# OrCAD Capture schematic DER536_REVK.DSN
size C; title: DER 536; rev: B
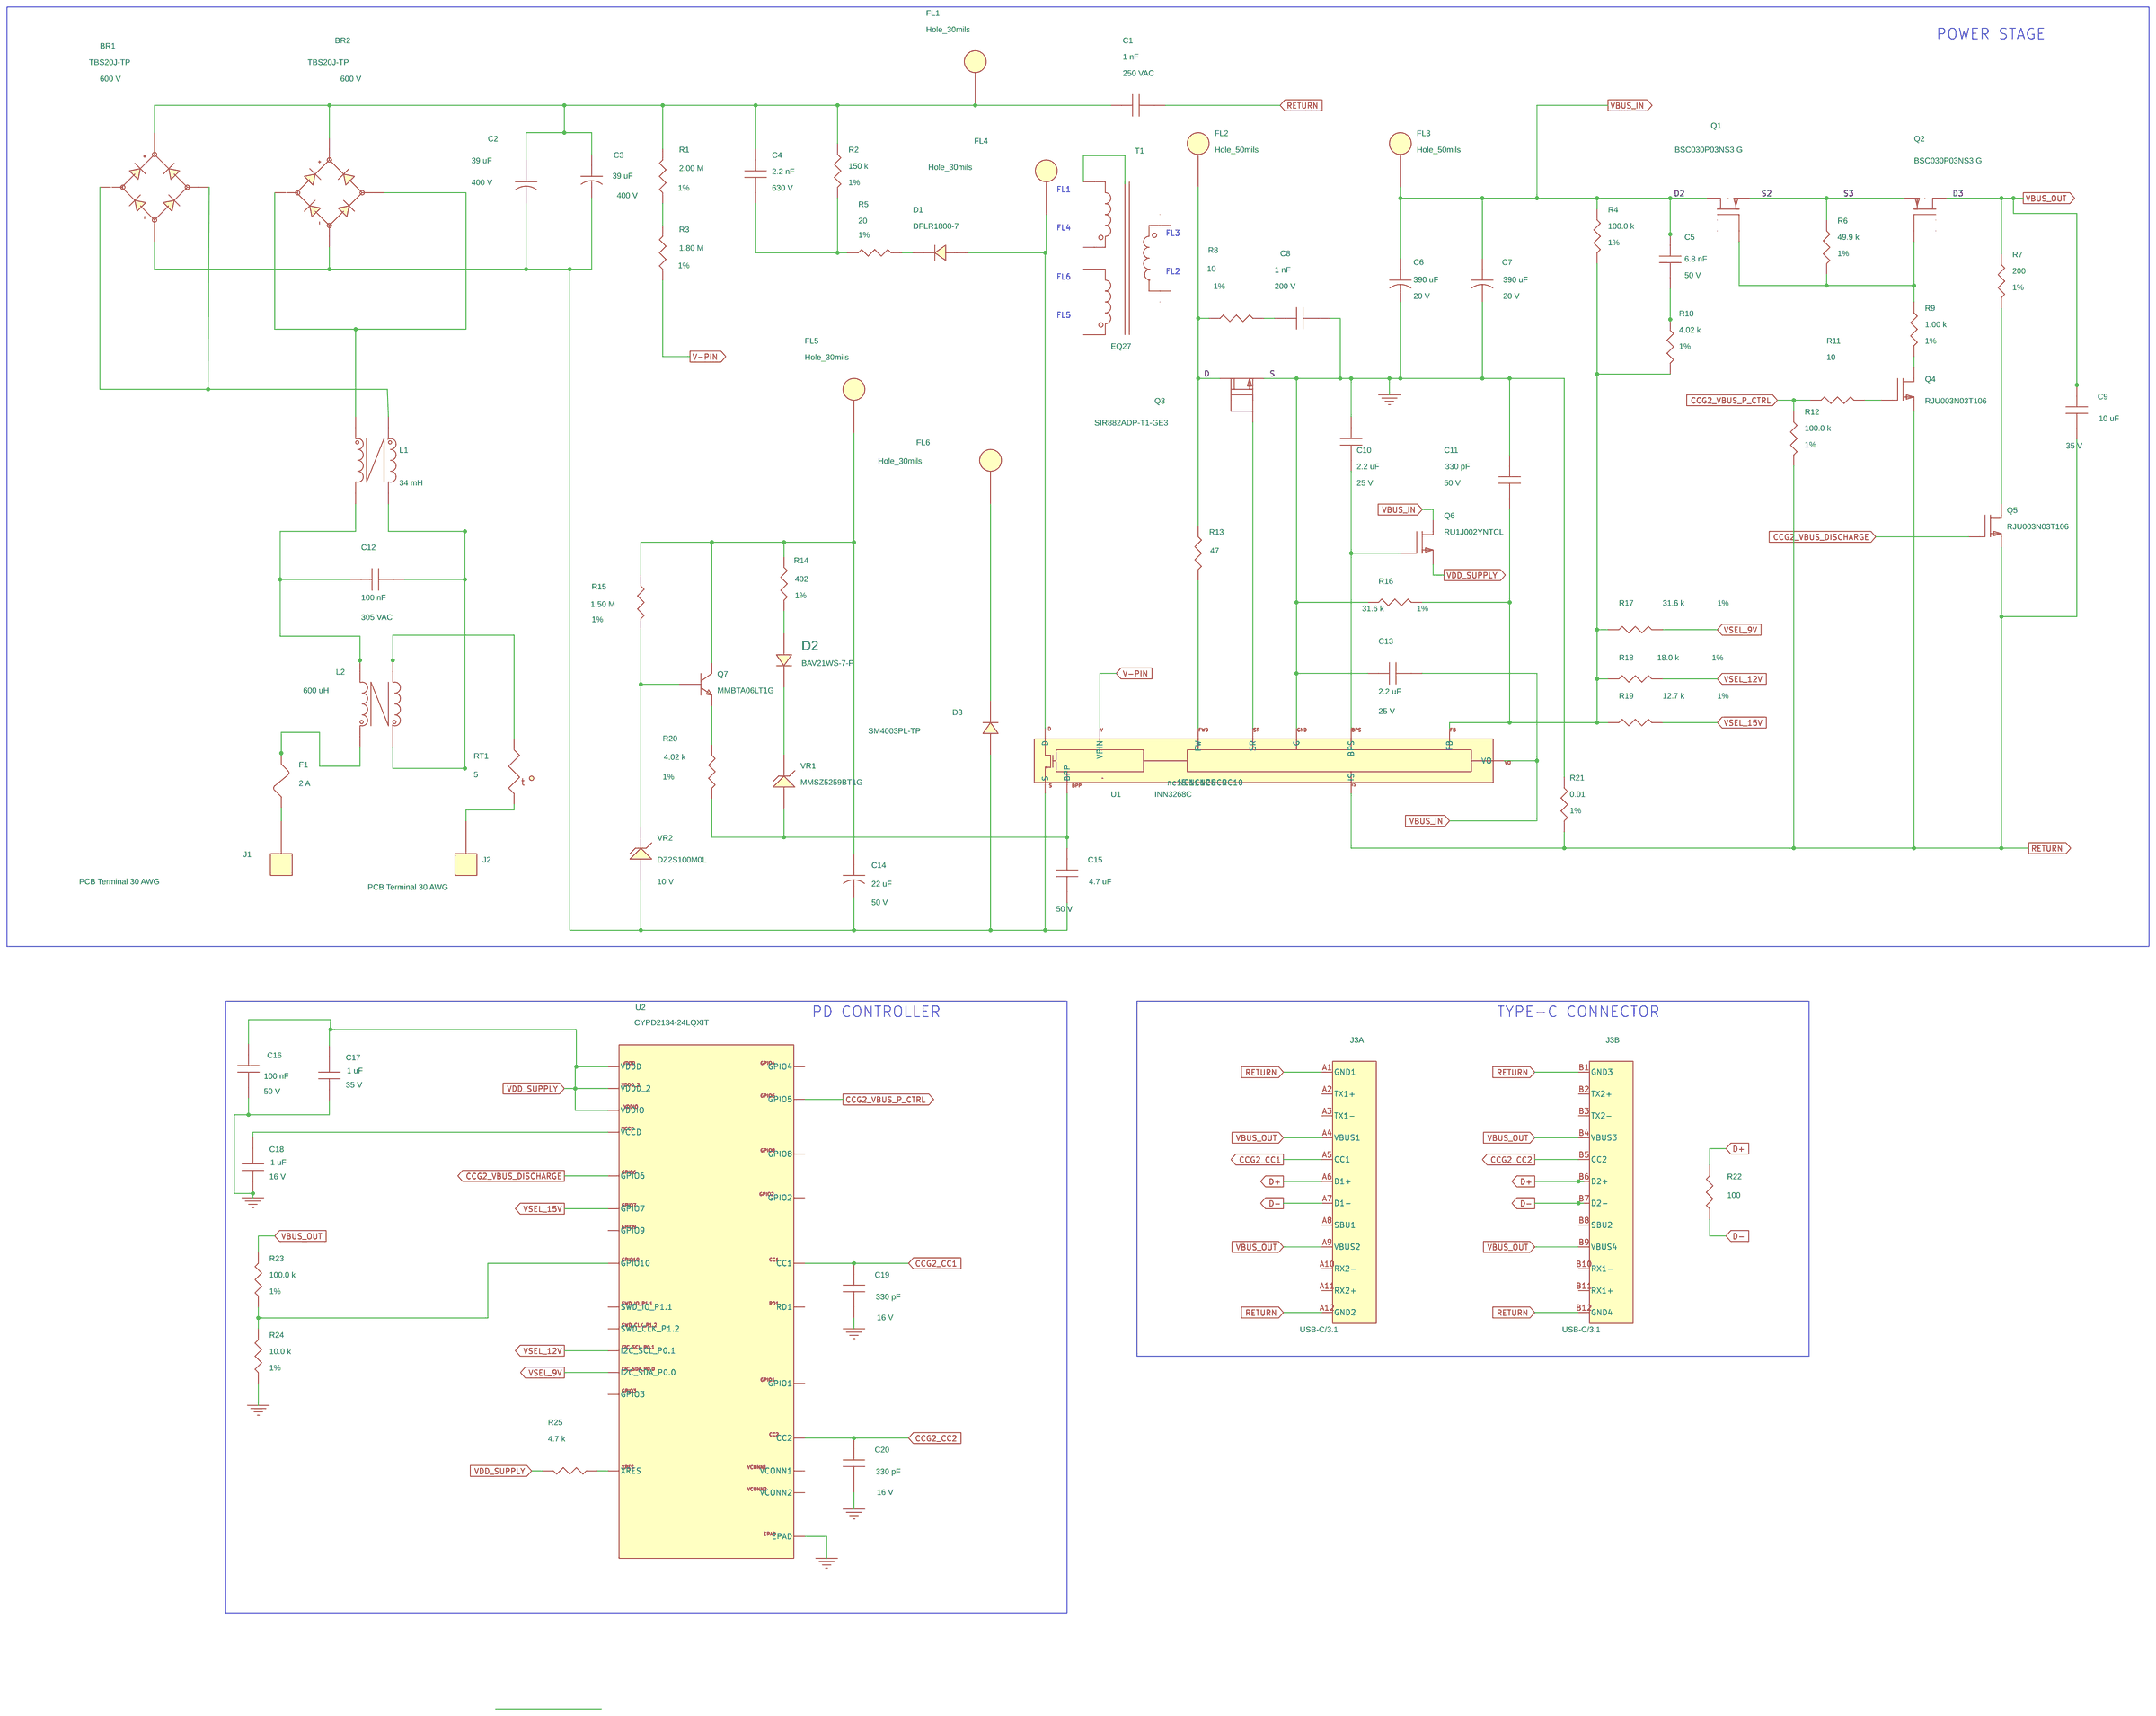
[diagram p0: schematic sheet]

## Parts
BR1  TBS20J-TP  [pismd_4-TBS]
BR2  TBS20J-TP  [pismd_4-TBS]
C1  1 nF  [pinpycaprad540x290ls400040h]
C2  39 uF  [PI_POLCAP315LS138D063]
C3  39 uF  [PI_POLCAP315LS138D063]
C4  2.2 nF  [pismc1206]
C5  6.8 nF  [pismc0603]
C6  390 uF  [pipolcapclyd320ls140030]
C7  390 uF  [pipolcapclyd320ls140030]
C8  1 nF  [pismc0805]
C9  10 uF  [pismc0805]
C10  2.2 uF  [pismc0805]
C11  330 pF  [pismc0603]
C12  100 nF  [pi_np_xcap_rad512x197x395d040_h]
C13  2.2 uF  [pismc0805]
C14  22 uF  [pipolcapclyd200ls80030h]
C15  4.7 uF  [pismc0805]
C16  100 nF  [pismc0603]
C17  1 uF  [pismc0603]
C18  1 uF  [pismc0805]
C19  330 pF  [pismr0402]
C20  330 pF  [pismr0402]
D1  DFLR1800-7  [pismddflr120012]
D2  BAV21WS-7-F  [pismsod323]
D3  SM4003PL-TP  [pi_sm_sod-123_12]
F1  2 A  [pi_rst_microfuse]
FL1  Hole_30mils  [pi_hole_30mil]
FL2  Hole_50mils  [pi_hole_50mil]
FL3  Hole_50mils  [pi_hole_50mil]
FL4  Hole_30mils  [pi_hole_30mil]
FL5  Hole_30mils  [pi_hole_30mil]
FL6  Hole_30mils  [pi_hole_30mil]
J1  PCB Terminal 30 AWG  [pi_hole_30awg]
J2  PCB Terminal 30 AWG  [pi_hole_30awg]
J3  USB-C/3.1  [pi_conn_usb_3p1_top]  (sections A,B)
L1  34 mH  [pi_CMChoke_19x10mmH]
L2  600 uH  [pi_toroid_CMC4p_H]
Q1  BSC030P03NS3 G  [pi_sm_pg-tdson-8]
Q2  BSC030P03NS3 G  [pi_sm_pg-tdson-8]
Q3  SIR882ADP-T1-GE3  [PI_SM_PowerPAK_SO-8_Single]
Q4  RJU003N03T106  [pismsot323]
Q5  RJU003N03T106  [pismsot323]
Q6  RU1J002YNTCL  [pi_sm_umt3f]
Q7  MMBTA06LT1G  [pismsot23123_1]
R1  2.00 M  [pismr1206]
R2  150 k  [pismr1206]
R3  1.80 M  [pismr1206]
R4  100.0 k  [pismr0402]
R5  20  [pismr1206]
R6  49.9 k  [pismr0402]
R7  200  [pismr1206]
R8  10  [pismr0805]
R9  1.00 k  [pismr0402]
R10  4.02 k  [pismr0603]
R11  10  [pismr0402]
R12  100.0 k  [pismr0402]
R13  47  [pismr0603]
R14  402  [pismr0603]
R15  1.50 M  [pismr0603]
R16  31.6 k  [pismr0402]
R17  31.6 k  [pismr0402]
R18  18.0 k  [pismr0402]
R19  12.7 k  [pismr0402]
R20  4.02 k  [pismr0603]
R21  0.01  [pismr0805]
R22  100  [pismr0402]
R23  100.0 k  [pismr0402]
R24  10.0 k  [pismr0402]
R25  4.7 k  [pismr0402]
RT1  5  [pi_rad_276DX197T_ls100d025]
T1  EQ27  [pi_PLANAR_E43-10-28_04]
U1  INN3268C  [pi_ic_insop_24d]
U2  CYPD2134-24LQXIT  [pi_sm_24_QFN]
VR1  MMSZ5259BT1G  [pi_sm_sod-123_12]
VR2  DZ2S100M0L  [pi_sm_d_ssmini2p]

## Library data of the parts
BR1 BR2 = DIODE_BRIDGE_+-~~: Disp_Voltage: 600 V; Part Number: 15-01174-00
C1 = CAP_NP: ALT_SYMBOLS: pinpycaprad540x290ls400040h,pinpycaprad500x220ls400040; COMPGROUP: 3; Disp_Voltage: 250 VAC; FPLIST: pinpycaprad540x290ls400040,pinpycaprad540x290ls400040h,pinpycaprad500x220ls400040; PCB Editor PCBFP: pinpycaprad540x290ls400040; Part Number: 20-00375-00; Voltage: 250 VAC
C2 C3 = CAP_POL: ALT_SYMBOLS: PI_POLCAP315LS138D063L2000H; Disp_Voltage: 400 V; FPLIST: PI_POLCAP315LS138D063,PI_POLCAP315LS138D063L2000H; Part Number: 20-08989-00; Voltage: 400 V
C4 = CAP_NP: Disp_Voltage: 630 V; Part Number: 20-08609-00; Voltage: 630 V
C5 = CAP_NP: Disp_Voltage: 50 V; Part Number: 20-08888-00; Voltage: 50 V
C6 C7 = CAP_POL: ALT_SYMBOLS: pipolcapclyd320ls140d30h470; Disp_Voltage: 20 V; FPLIST: pipolcapclyd320ls140030,pipolcapclyd320ls140d30h470; Part Number: 20-08769-00; Voltage: 20 V
C8 = CAP_NP: Disp_Voltage: 200 V; PCB Editor PCBFP: pismc0603; Part Number: 20-00737-00; Voltage: 200 V
C9 = CAP_NP: Disp_Voltage: 35 V; Part Number: 20-08720-00; Voltage: 35 V
C10 C13 = CAP_NP: Disp_Voltage: 25 V; Part Number: 20-08603-00; Voltage: 25 V
C11 = CAP_NP: Disp_Voltage: 50 V; Part Number: 20-08676-00; Voltage: 50 V
C12 = CAP_NP: Disp_Voltage: 305 VAC; FPLIST: pi_np_xcap_rad512x197x395d040,pi_np_xcap_rad512x197x395d040_h; Part Number: 20-08957-00; Voltage: 305 VAC
C14 = CAP_POL: Disp_Voltage: 50 V; FPLIST: pipolcapclyd200ls80030,pipolcapclyd200ls80030h; Part Number: 20-00056-00; Voltage: 50 V
C15 = CAP_NP: Disp_Voltage: 50 V; Part Number: 20-01130-00; Voltage: 50 V
C16 = CAP_NP: Disp_Voltage: 50 V; Part Number: 20-00936-00; Voltage: 50 V
C17 = CAP_NP: Disp_Voltage: 35 V; Part Number: 20-01134-00; Voltage: 35 V
C18 = CAP_NP: Disp_Voltage: 16 V; Part Number: 20-01331-00; Voltage: 16 V
C19 C20 = CAP_NP: Disp_Voltage: 16 V; Part Number: 20-08910-00; Voltage: 16 V
D1 = DIODE: Part Number: 15-00919-00
D2 = DIODE: COMPGROUP: 1; Part Number: 15-00385-00
D3 = DIODE: COMPGROUP: 1; Part Number: 15-01052-00
F1 = FUSE: ALT_SYMBOLS: pirstmicrofusehoz; FPLIST: pi_rst_microfuse,pirstmicrofusehoz; Part Number: 40-00021-00
FL1 FL4-FL6 = FlyingLead: Part Number: 35-00284-00
FL2 FL3 = FlyingLead: Part Number: 35-00283-00
J1 J2 = TERM_1Pin: Part Number: 35-00026-00
J3 = CON24_USB: ALT_SYMBOLS: pi_conn_usb_3p1_topD; FPLIST: pi_conn_usb_3p1_top,pi_conn_usb_3p1_topD; Part Number: 35-00354-00
L1 = TORRID_4P_12_34: FPLIST: pi_CMChoke_19x10mm,pi_CMChoke_19x10mmH; Part Number: 32-00345-00
L2 = TORRID_4P_12_34: ALT_SYMBOLS: pi_toroid_CMC4p_V; FPLIST: pi_toroid_CMC4p_H,pi_toroid_CMC4p_V; Part Number: 32-00347-00
Q1 = FET_P_TDSON-8_15: Part Number: 50-00176-00
Q2 = FET_P_TDSON-8_16: Part Number: 50-00176-00
Q3 = FET_N_SGD_123_4_5678: Part Number: 50-00142-00
Q4 Q5 = FET_N_SGD: Part Number: 50-00177-00
Q6 = FET_N_GSD: Part Number: 50-00199-00
Q7 = NPN_BEC: Part Number: 55-00072-00
R1 = R: Disp_Tol: 1%; Part Number: 05-03156-00
R2 = R: Disp_Tol: 1%; Part Number: 05-00402-00
R3 = R: Disp_Tol: 1%; Part Number: 05-03155-00
R4 R12 = R: Disp_Tol: 1%; Part Number: 05-06039-00
R5 = R: Disp_Tol: 1%; Part Number: 05-00030-00
R6 = R: Disp_Tol: 1%; Part Number: 05-06006-00
R7 = R: Disp_Tol: 1%; Part Number: 05-00126-00
R8 = R: Disp_Tol: 1%; Part Number: 05-00492-00
R9 = R: Disp_Tol: 1%; Part Number: 05-05823-00
R10 R20 = R: Disp_Tol: 1%; Part Number: 05-01136-00
R11 = R: Part Number: 05-03538-00
R13 = R: Part Number: 05-01656-00
R14 = R: Disp_Tol: 1%; Part Number: 05-01040-00
R15 = R: Disp_Tol: 1%; Part Number: 05-03144-00
R16 R17 = R: Disp_Tol: 1%; Part Number: 05-05986-00
R18 = R: Disp_Tol: 1%; Part Number: 05-05961-00
R19 = R: Disp_Tol: 1%; Part Number: 05-05945-00
R21 = R: Disp_Tol: 1%; Part Number: 05-06341-00
R22 = R: Part Number: 05-06192-00
R23 = R: RES SMD 100K OHM 1% 1/10W 0402; DIGI-KEY PART NO: P100KLCT-ND; Disp_Tol: 1%; MFG Part number: ERJ-2RKF1003X; Manufacturer: Panasonic Electronic Components; Part Number: 05-06039-00; Price: 0.1
R24 = R: RES SMD 10K OHM 1% 1/10W 0402; DIGI-KEY PART NO: P10.0KLCT-ND; Disp_Tol: 1%; MFG Part number: ERJ-2RKF1002X; Manufacturer: Panasonic Electronic Components; Part Number: 05-05935-00; Price: 0.1
R25 = R: Part Number: 05-06228-00
RT1 = THERMISTOR: Part Number: 91-00009-00
T1 = Transformer_Planar_3WDG_0: Part Number: 25-01125-00
U1 = DEV_Inno3CP: Part Number: 10-01044-00
U2 = CYPD2134-24LQXIT: Part Number: 45-00329-00
VR1 = DIODE_ZENER: Part Number: 15-01100-00
VR2 = DIODE_ZENER: Disp_Voltage: 10 V; Part Number: 15-00926-00

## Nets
GND: C6.2 C7.2 C8.2 C10.1 C11.1 C13.1 C16.2 C17.1 C18.1 C19.2 C20.2 Q3.1(S) Q3.2(S) Q3.3(S) R16.1 R21.1 R24.2 U1.2(G) U2.25(EPAD)
VDD_SUPPLY: C16.1 C17.2 Q6.2(S) R25.2 U2.6(VDDD) U2.8(VDDIO) U2.9(VDDD_2)
CCG2_CC1: C19.1 J3.A5(CC1) U2.2(CC1)
CCG2_CC2: C20.1 J3.B5(CC2) U2.1(CC2)
CCG2_VBUS_DISCHARGE: Q5.2(G) U2.18(GPIO6)
CCG2_VBUS_P_CTRL: R11.1 R12.1 U2.17(GPIO5)
D: FL2.1 Q3.5(D) Q3.6(D) Q3.7(D) Q3.8(D) R8.2 R13.1
D2: C5.1 C6.1 C7.1 C13.2 FL3.1 Q1.5(D2) Q1.6(D2) Q1.7(D2) Q1.8(D2) Q6.3(D) R4.1 U1.6(VO)
D3: C9.1 J3.A4(VBUS1) J3.A9(VBUS2) J3.B4(VBUS3) J3.B9(VBUS4) Q2.5(D3) Q2.6(D3) Q2.7(D3) Q2.8(D3) R7.1 R23.1
D+: J3.A6(D1+) J3.B6(D2+) R22.2
D-: J3.A7(D1-) J3.B7(D2-) R22.1
NC8: U1.8(NC8)
NC9: U1.9(NC9)
NC10: U1.10(NC10)
NC11: U1.11(NC11)
NC12: U1.12(NC12)
NC15: U1.15(nc15)
RETURN: C1.2 C9.2 J3.A1(GND1) J3.A12(GND2) J3.B1(GND3) J3.B12(GND4) Q4.1(S) Q5.1(S) R12.2 R21.2 U1.1(IS)
S2: Q1.1(S1) Q1.2(S2) Q1.3(S3) Q2.1(S1) Q2.2(S2) Q2.3(S3) R6.1
V-PIN: R3.1 U1.13(VPIN)
VSEL_9V: R17.2 U2.19(I2C_SDA_P0.0)
VSEL_12V: R18.2 U2.20(I2C_SCL_P0.1)
VSEL_15V: R19.2 U2.21(GPIO7)
N9603673: BR1.1 BR2.1 C1.1 C2.1 C3.1 C4.1 FL1.1 R1.2 R2.1
N10010568: BR1.2 BR2.2 C2.2 C3.2 C14.2 C15.2 D3.2 U1.16(S) VR2.2
N10479111: F1.1 J1.1
N10806149: C15.1 R20.2 U1.14(BPP) VR1.2
N10809540: Q3.4(G) U1.5(SR)
N10810926: C11.2 R4.2 R10.2 R16.2 R17.1 R18.1 R19.1 U1.3(FB)
N10813018: R1.1 R3.2
N10869805: C10.2 Q6.1(G) U1.4(BPS)
N10873526: R13.2 U1.7(FW)
N10908947: BR2.3 BR2.4 L1.1
N10950053: C14.1 FL5.1 Q7.3(COLLECTOR) R14.1 R15.1
N10950141: Q7.2(EMITTER) R20.1
N10950189: Q7.1(BASE) R15.2 VR2.1
N10955093: C12.1 L1.2 L2.2
N10964883: C8.1 R8.1
N10966650: D1.2 FL4.1 U1.24(D)
N10967740: C4.2 R2.2 R5.1
N11001432: Q1.4(G) Q2.4(G) R6.2 R9.1
N11001460: Q4.2(G) R11.2
N11001464: Q5.3(D) R7.2
N11001472: Q4.3(D) R9.2
N11008304: R23.2 R24.1 U2.24(GPIO10)
N11008330: C18.2 U2.7(VCCD)
N11008640: R25.1 U2.16(XRES)
N11015378: C12.2 L1.4 L2.3
N11036082: D1.1 R5.2
N11061897: D3.1 FL6.1
N11077431: D2.2 R14.2
N11077448: D2.1 VR1.1
N11084818: BR1.3 BR1.4 L1.3
N11096040: C5.2 R10.1
N11100718: J2.1 RT1.2
N11100857: F1.2 L2.1
N11100955: L2.4 RT1.1

Not connected (* = marked no-connect by the designer): J3 A2(TX1+) A3(TX1-) A8(SBU1) A10(RX2-) A11(RX2+) B2(TX2+) B3(TX2-) B8(SBU2) B10(RX1-) B11(RX1+); T1 1 2 3 4 5 6 7 8; U2 3(RD1) 4(VCONN2) 5(VCONN1) 10(GPIO1) 11(SWD_IO_P1.1) 12(SWD_CLK_P1.2) 13(GPIO2) 14(GPIO3) 15(GPIO4) 22(GPIO8) 23(GPIO9)

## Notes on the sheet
- POWER STAGE
- FL1
- FL4
- FL3
- FL6
- FL2
- FL5
- PD CONTROLLER
- TYPE-C CONNECTOR
